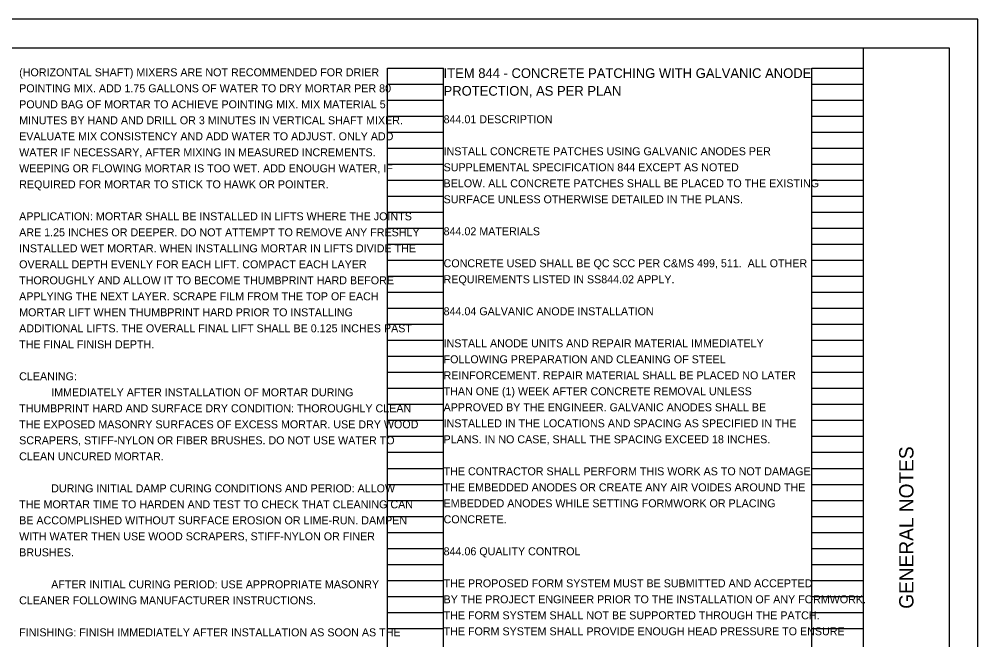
# Model space of a CAD drawing. Extents: x 0 to 59.1, y 0 to 43.6.
# Drawn here: x 17.24 to 34, y 11.14 to 22 of the extents above; entities that cross this region are included whole.
import ezdxf

# ---------------------------------------------------------------- set-up
doc = ezdxf.new("R2010")
doc.units = 0
for name, color, linetype in [('BR_P_Gen_Text', 7, 'Continuous'), ('SH_Border', 7, 'Continuous'), ('SH_Cut_Line', 7, 'Continuous'), ('SH_Data', 7, 'Continuous'), ('SH_Text', 7, 'Continuous')]:
    doc.layers.add(name, color=color, linetype=linetype)

msp = doc.modelspace()

# ---------------------------------------------------------------- linework, layer by layer
at = {"layer": 'SH_Border'}
msp.add_line((32, 0.5), (32, 21.5), dxfattribs=at)
msp.add_lwpolyline([(1.5, 21.5), (33.5, 21.5), (33.5, 0.5), (1.5, 0.5)], close=True, dxfattribs=at)
at = {"layer": 'SH_Cut_Line'}
msp.add_lwpolyline([(0, 0), (34, 0), (34, 22), (0, 22)], close=True, dxfattribs=at)
at = {"layer": 'SH_Data'}
for p, q in [((23.68, 0.98), (23.68, 21.14)), ((23.68, 21.14), (24.66, 21.14)), ((24.66, 0.98), (24.66, 21.14)), ((31.1, 0.98), (31.1, 21.14)), ((31.1, 21.14), (32, 21.14)), ((32, 0.98), (32, 21.14)), ((23.68, 20.86), (24.66, 20.86)), ((31.1, 20.86), (32, 20.86)), ((23.68, 20.58), (24.66, 20.58)), ((31.1, 20.58), (32, 20.58)), ((23.68, 20.3), (24.66, 20.3)), ((31.1, 20.3), (32, 20.3)), ((23.68, 20.02), (24.66, 20.02)), ((31.1, 20.02), (32, 20.02)), ((23.68, 19.74), (24.66, 19.74)), ((31.1, 19.74), (32, 19.74)), ((23.68, 19.46), (24.66, 19.46)), ((31.1, 19.46), (32, 19.46)), ((23.68, 19.18), (24.66, 19.18)), ((31.1, 19.18), (32, 19.18)), ((23.68, 18.9), (24.66, 18.9)), ((31.1, 18.9), (32, 18.9)), ((23.68, 18.62), (24.66, 18.62)), ((31.1, 18.62), (32, 18.62)), ((23.68, 18.34), (24.66, 18.34)), ((31.1, 18.34), (32, 18.34)), ((23.68, 18.06), (24.66, 18.06)), ((31.1, 18.06), (32, 18.06)), ((23.68, 17.78), (24.66, 17.78)), ((31.1, 17.78), (32, 17.78)), ((23.68, 17.5), (24.66, 17.5)), ((31.1, 17.5), (32, 17.5)), ((23.68, 17.22), (24.66, 17.22)), ((31.1, 17.22), (32, 17.22)), ((23.68, 16.94), (24.66, 16.94)), ((31.1, 16.94), (32, 16.94)), ((23.68, 16.66), (24.66, 16.66)), ((31.1, 16.66), (32, 16.66)), ((23.68, 16.38), (24.66, 16.38)), ((31.1, 16.38), (32, 16.38)), ((23.68, 16.1), (24.66, 16.1)), ((31.1, 16.1), (32, 16.1)), ((23.68, 15.82), (24.66, 15.82)), ((31.1, 15.82), (32, 15.82)), ((23.68, 15.54), (24.66, 15.54)), ((31.1, 15.54), (32, 15.54)), ((23.68, 15.26), (24.66, 15.26)), ((31.1, 15.26), (32, 15.26)), ((23.68, 14.98), (24.66, 14.98)), ((31.1, 14.98), (32, 14.98)), ((23.68, 14.7), (24.66, 14.7)), ((31.1, 14.7), (32, 14.7)), ((23.68, 14.42), (24.66, 14.42)), ((31.1, 14.42), (32, 14.42)), ((23.68, 14.14), (24.66, 14.14)), ((31.1, 14.14), (32, 14.14)), ((23.68, 13.86), (24.66, 13.86)), ((31.1, 13.86), (32, 13.86)), ((23.68, 13.58), (24.66, 13.58)), ((31.1, 13.58), (32, 13.58)), ((23.68, 13.3), (24.66, 13.3)), ((31.1, 13.3), (32, 13.3)), ((23.68, 13.02), (24.66, 13.02)), ((31.1, 13.02), (32, 13.02)), ((23.68, 12.74), (24.66, 12.74)), ((31.1, 12.74), (32, 12.74)), ((23.68, 12.46), (24.66, 12.46)), ((31.1, 12.46), (32, 12.46)), ((23.68, 12.18), (24.66, 12.18)), ((31.1, 12.18), (32, 12.18)), ((23.68, 11.9), (24.66, 11.9)), ((31.1, 11.9), (32, 11.9)), ((23.68, 11.62), (24.66, 11.62)), ((31.1, 11.62), (32, 11.62)), ((23.68, 11.34), (24.66, 11.34)), ((31.1, 11.34), (32, 11.34))]:
    msp.add_line(p, q, dxfattribs=at)

# ---------------------------------------------------------------- texts
at = {"layer": 'BR_P_Gen_Text'}
for s, height, p in [('ITEM 844 - CONCRETE PATCHING WITH GALVANIC ANODE', 0.17, (24.66, 20.97)), ('PROTECTION, AS PER PLAN', 0.17, (24.66, 20.66)), ('844.01 DESCRIPTION', 0.14, (24.66, 20.178)), ('INSTALL CONCRETE PATCHES USING GALVANIC ANODES PER', 0.14, (24.66, 19.618)), ('SUPPLEMENTAL SPECIFICATION 844 EXCEPT AS NOTED ', 0.14, (24.66, 19.338)), ('BELOW. ALL CONCRETE PATCHES SHALL BE PLACED TO THE EXISTING ', 0.14, (24.66, 19.058)), ('SURFACE UNLESS OTHERWISE DETAILED IN THE PLANS.  ', 0.14, (24.66, 18.778)), ('844.02 MATERIALS ', 0.14, (24.66, 18.218)), ('CONCRETE USED SHALL BE QC SCC PER C&MS 499, 511.  ALL OTHER ', 0.14, (24.66, 17.658)), ('REQUIREMENTS LISTED IN SS844.02 APPLY.  ', 0.14, (24.66, 17.378)), ('844.04 GALVANIC ANODE INSTALLATION', 0.14, (24.66, 16.818)), ('INSTALL ANODE UNITS AND REPAIR MATERIAL IMMEDIATELY', 0.14, (24.66, 16.258)), ('FOLLOWING PREPARATION AND CLEANING OF STEEL', 0.14, (24.66, 15.978)), ('REINFORCEMENT. REPAIR MATERIAL SHALL BE PLACED NO LATER', 0.14, (24.66, 15.698)), ('THAN ONE (1) WEEK AFTER CONCRETE REMOVAL UNLESS', 0.14, (24.66, 15.418)), ('APPROVED BY THE ENGINEER. GALVANIC ANODES SHALL BE', 0.14, (24.66, 15.138)), ('INSTALLED IN THE LOCATIONS AND SPACING AS SPECIFIED IN THE', 0.14, (24.66, 14.858)), ('PLANS. IN NO CASE, SHALL THE SPACING EXCEED 18 INCHES.', 0.14, (24.66, 14.578)), ('THE CONTRACTOR SHALL PERFORM THIS WORK AS TO NOT DAMAGE', 0.14, (24.66, 14.018)), ('THE EMBEDDED ANODES OR CREATE ANY AIR VOIDES AROUND THE', 0.14, (24.66, 13.738)), ('EMBEDDED ANODES WHILE SETTING FORMWORK OR PLACING', 0.14, (24.66, 13.458)), ('CONCRETE.', 0.14, (24.66, 13.178)), ('844.06 QUALITY CONTROL', 0.14, (24.66, 12.618)), ('THE PROPOSED FORM SYSTEM MUST BE SUBMITTED AND ACCEPTED ', 0.14, (24.66, 12.058)), ('BY THE PROJECT ENGINEER PRIOR TO THE INSTALLATION OF ANY FORMWORK.', 0.14, (24.66, 11.778)), ('THE FORM SYSTEM SHALL NOT BE SUPPORTED THROUGH THE PATCH. ', 0.14, (24.66, 11.498)), ('THE FORM SYSTEM SHALL PROVIDE ENOUGH HEAD PRESSURE TO ENSURE', 0.14, (24.66, 11.218))]:
    msp.add_text(s, height=height, dxfattribs=at).set_placement(p)
at = {"layer": 'SH_Data'}
msp.add_text('GENERAL NOTES', height=0.25, rotation=90, dxfattribs=at).set_placement((32.875, 11.682))
at = {"layer": 'SH_Text'}
for s, p in [('(HORIZONTAL SHAFT) MIXERS ARE NOT RECOMMENDED FOR DRIER ', (17.24, 21)), ('POINTING MIX. ADD 1.75 GALLONS OF WATER TO DRY MORTAR PER 80 ', (17.24, 20.72)), ('POUND BAG OF MORTAR TO ACHIEVE POINTING MIX. MIX MATERIAL 5 ', (17.24, 20.44)), ('MINUTES BY HAND AND DRILL OR 3 MINUTES IN VERTICAL SHAFT MIXER. ', (17.24, 20.16)), ('EVALUATE MIX CONSISTENCY AND ADD WATER TO ADJUST. ONLY ADD ', (17.24, 19.88)), ('WATER IF NECESSARY, AFTER MIXING IN MEASURED INCREMENTS. ', (17.24, 19.6)), ('WEEPING OR FLOWING MORTAR IS TOO WET. ADD ENOUGH WATER, IF ', (17.24, 19.32)), ('REQUIRED FOR MORTAR TO STICK TO HAWK OR POINTER. ', (17.24, 19.04)), ('APPLICATION: MORTAR SHALL BE INSTALLED IN LIFTS WHERE THE JOINTS ', (17.24, 18.48)), ('ARE 1.25 INCHES OR DEEPER. DO NOT ATTEMPT TO REMOVE ANY FRESHLY ', (17.24, 18.2)), ('INSTALLED WET MORTAR. WHEN INSTALLING MORTAR IN LIFTS DIVIDE THE ', (17.24, 17.92)), ('OVERALL DEPTH EVENLY FOR EACH LIFT. COMPACT EACH LAYER ', (17.24, 17.64)), ('THOROUGHLY AND ALLOW IT TO BECOME THUMBPRINT HARD BEFORE ', (17.24, 17.36)), ('APPLYING THE NEXT LAYER. SCRAPE FILM FROM THE TOP OF EACH ', (17.24, 17.08)), ('MORTAR LIFT WHEN THUMBPRINT HARD PRIOR TO INSTALLING ', (17.24, 16.8)), ('ADDITIONAL LIFTS. THE OVERALL FINAL LIFT SHALL BE 0.125 INCHES PAST ', (17.24, 16.52)), ('THE FINAL FINISH DEPTH.', (17.24, 16.24)), ('CLEANING: ', (17.24, 15.68)), ('IMMEDIATELY AFTER INSTALLATION OF MORTAR DURING ', (17.8, 15.4)), ('THUMBPRINT HARD AND SURFACE DRY CONDITION: THOROUGHLY CLEAN ', (17.24, 15.12)), ('THE EXPOSED MASONRY SURFACES OF EXCESS MORTAR. USE DRY WOOD ', (17.24, 14.84)), ('SCRAPERS, STIFF-NYLON OR FIBER BRUSHES. DO NOT USE WATER TO ', (17.24, 14.56)), ('CLEAN UNCURED MORTAR.', (17.24, 14.28)), ('DURING INITIAL DAMP CURING CONDITIONS AND PERIOD: ALLOW ', (17.8, 13.72)), ('THE MORTAR TIME TO HARDEN AND TEST TO CHECK THAT CLEANING CAN ', (17.24, 13.44)), ('BE ACCOMPLISHED WITHOUT SURFACE EROSION OR LIME-RUN. DAMPEN ', (17.24, 13.16)), ('WITH WATER THEN USE WOOD SCRAPERS, STIFF-NYLON OR FINER ', (17.24, 12.88)), ('BRUSHES.', (17.24, 12.6)), ('AFTER INITIAL CURING PERIOD: USE APPROPRIATE MASONRY ', (17.8, 12.04)), ('CLEANER FOLLOWING MANUFACTURER INSTRUCTIONS.', (17.24, 11.76)), ('FINISHING: FINISH IMMEDIATELY AFTER INSTALLATION AS SOON AS THE ', (17.24, 11.2))]:
    msp.add_text(s, height=0.14, dxfattribs=at).set_placement(p)

doc.saveas('drawing.dxf')
